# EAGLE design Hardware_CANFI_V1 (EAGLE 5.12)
DIELECTRIC: X5R; OC_FARNELL: unknown; OC_RADIOSPARES: 8006936; SUPPLIER: COILCRAFT; VOLTAGE: 16V

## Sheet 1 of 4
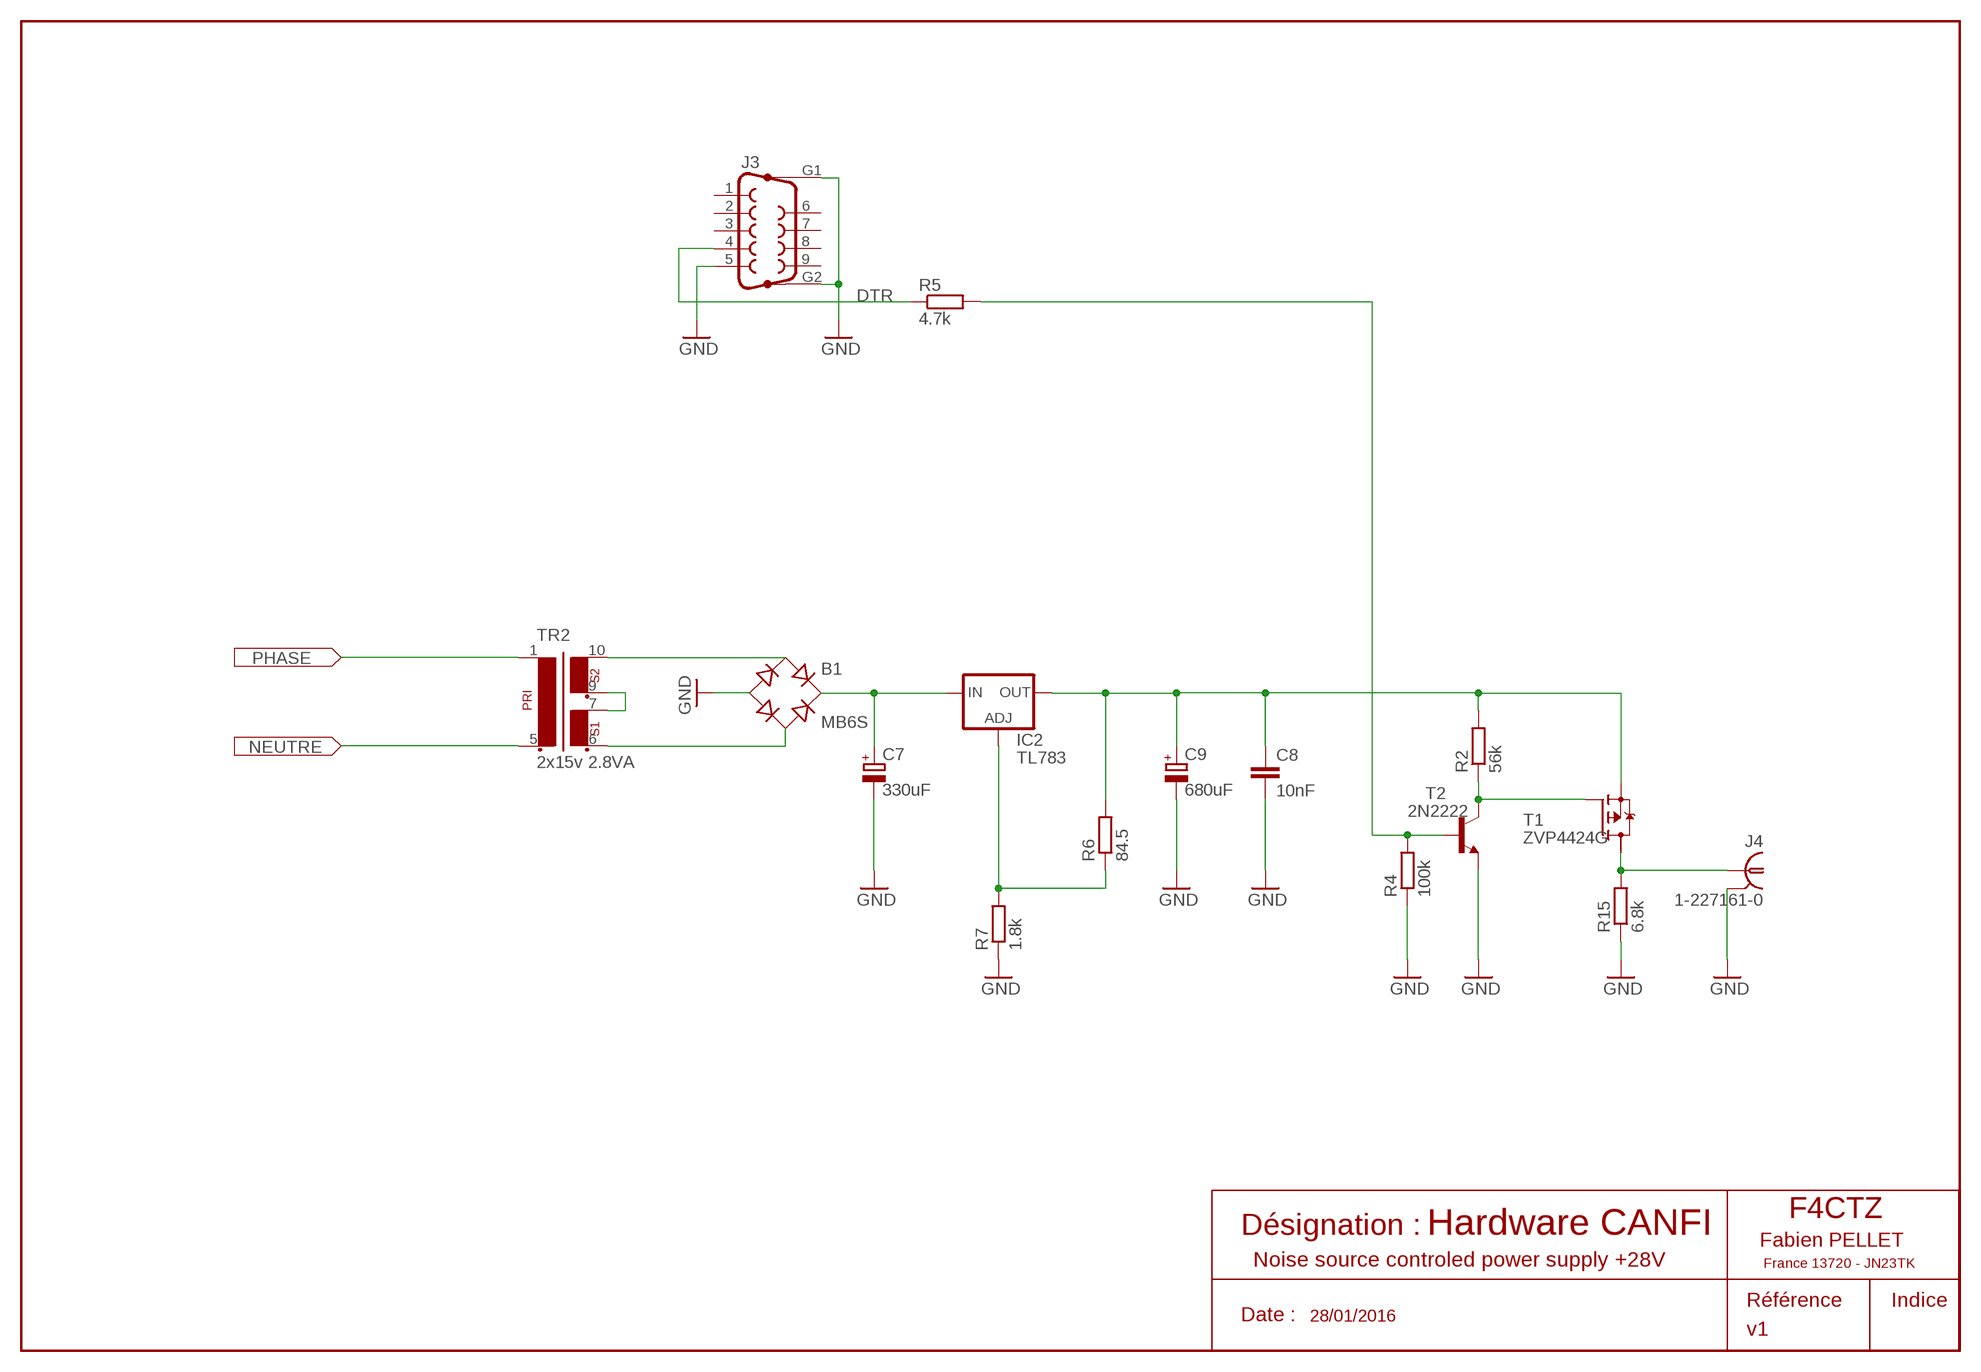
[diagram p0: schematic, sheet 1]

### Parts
B1  MB6S  MB8S  [SOIC-4]
C7  330uF  CPOL-EUE5-13  [E5-13]
C8  10nF  C-EUC0603  [C0603]
C9  680uF  CPOL-EUE5-10.5  [E5-10,5]
IC2  TL783  LM317TS  [317TS]
J3  F09HP  [F09HP]
J4  1-227161-0  [AMP_227161]
R2  56k  R-EU_R0603  [R0603]
R4  100k  R-EU_R0603  [R0603]
R5  4.7k  R-EU_R0603  [R0603]
R6  84.5  R-EU_R0603  [R0603]
R7  1.8k  R-EU_R0603  [R0603]
R15  6.8k  R-EU_R0603  [R0603]
T1  ZVP4424G  BSP170P  [SOT223]
T2  2N2222  2N2222-NPN-TO92-EBC  [TO92-EBC]
TR2  2x15v 2.8VA  EI30-2  [EI30-2]

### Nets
DTR: J3.4 R5.1
GND: B1.- C7.- C8.2 C9.- J3.5 J3.G1 J3.G2 J4.2(GND) R4.1 R7.1 R15.1 T2.E ; also sheet 2,3
N$8: R4.2 R5.2 T2.B
N$10: R2.1 T1.1(G) T2.C
N$12 [ALIM]: B1.~1(AC1) TR2.10
N$13 [ALIM]: TR2.7 TR2.9
N$14 [ALIM]: B1.~2(AC2) TR2.6
N$15 [ALIM]: C8.1 C9.+ IC2.2(OUT) R2.2 R6.2 T1.3(S)
N$18: IC2.1(ADJ) R6.1 R7.2
N$19 [ALIM]: B1.+ C7.+ IC2.3(IN)
N$21: J4.1 R15.2 T1.4(D1)
NEUTRE [HIGH_VOLTAGE]: TR2.5 ; also sheet 3
PHASE [HIGH_VOLTAGE]: TR2.1 ; also sheet 3
Unconnected: J3.1 J3.2 J3.3 J3.6 J3.7 J3.8 J3.9 T1.2(D)

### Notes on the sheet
- Hardware CANFI
- Noise source controled power supply +28V
- 28/01/2016

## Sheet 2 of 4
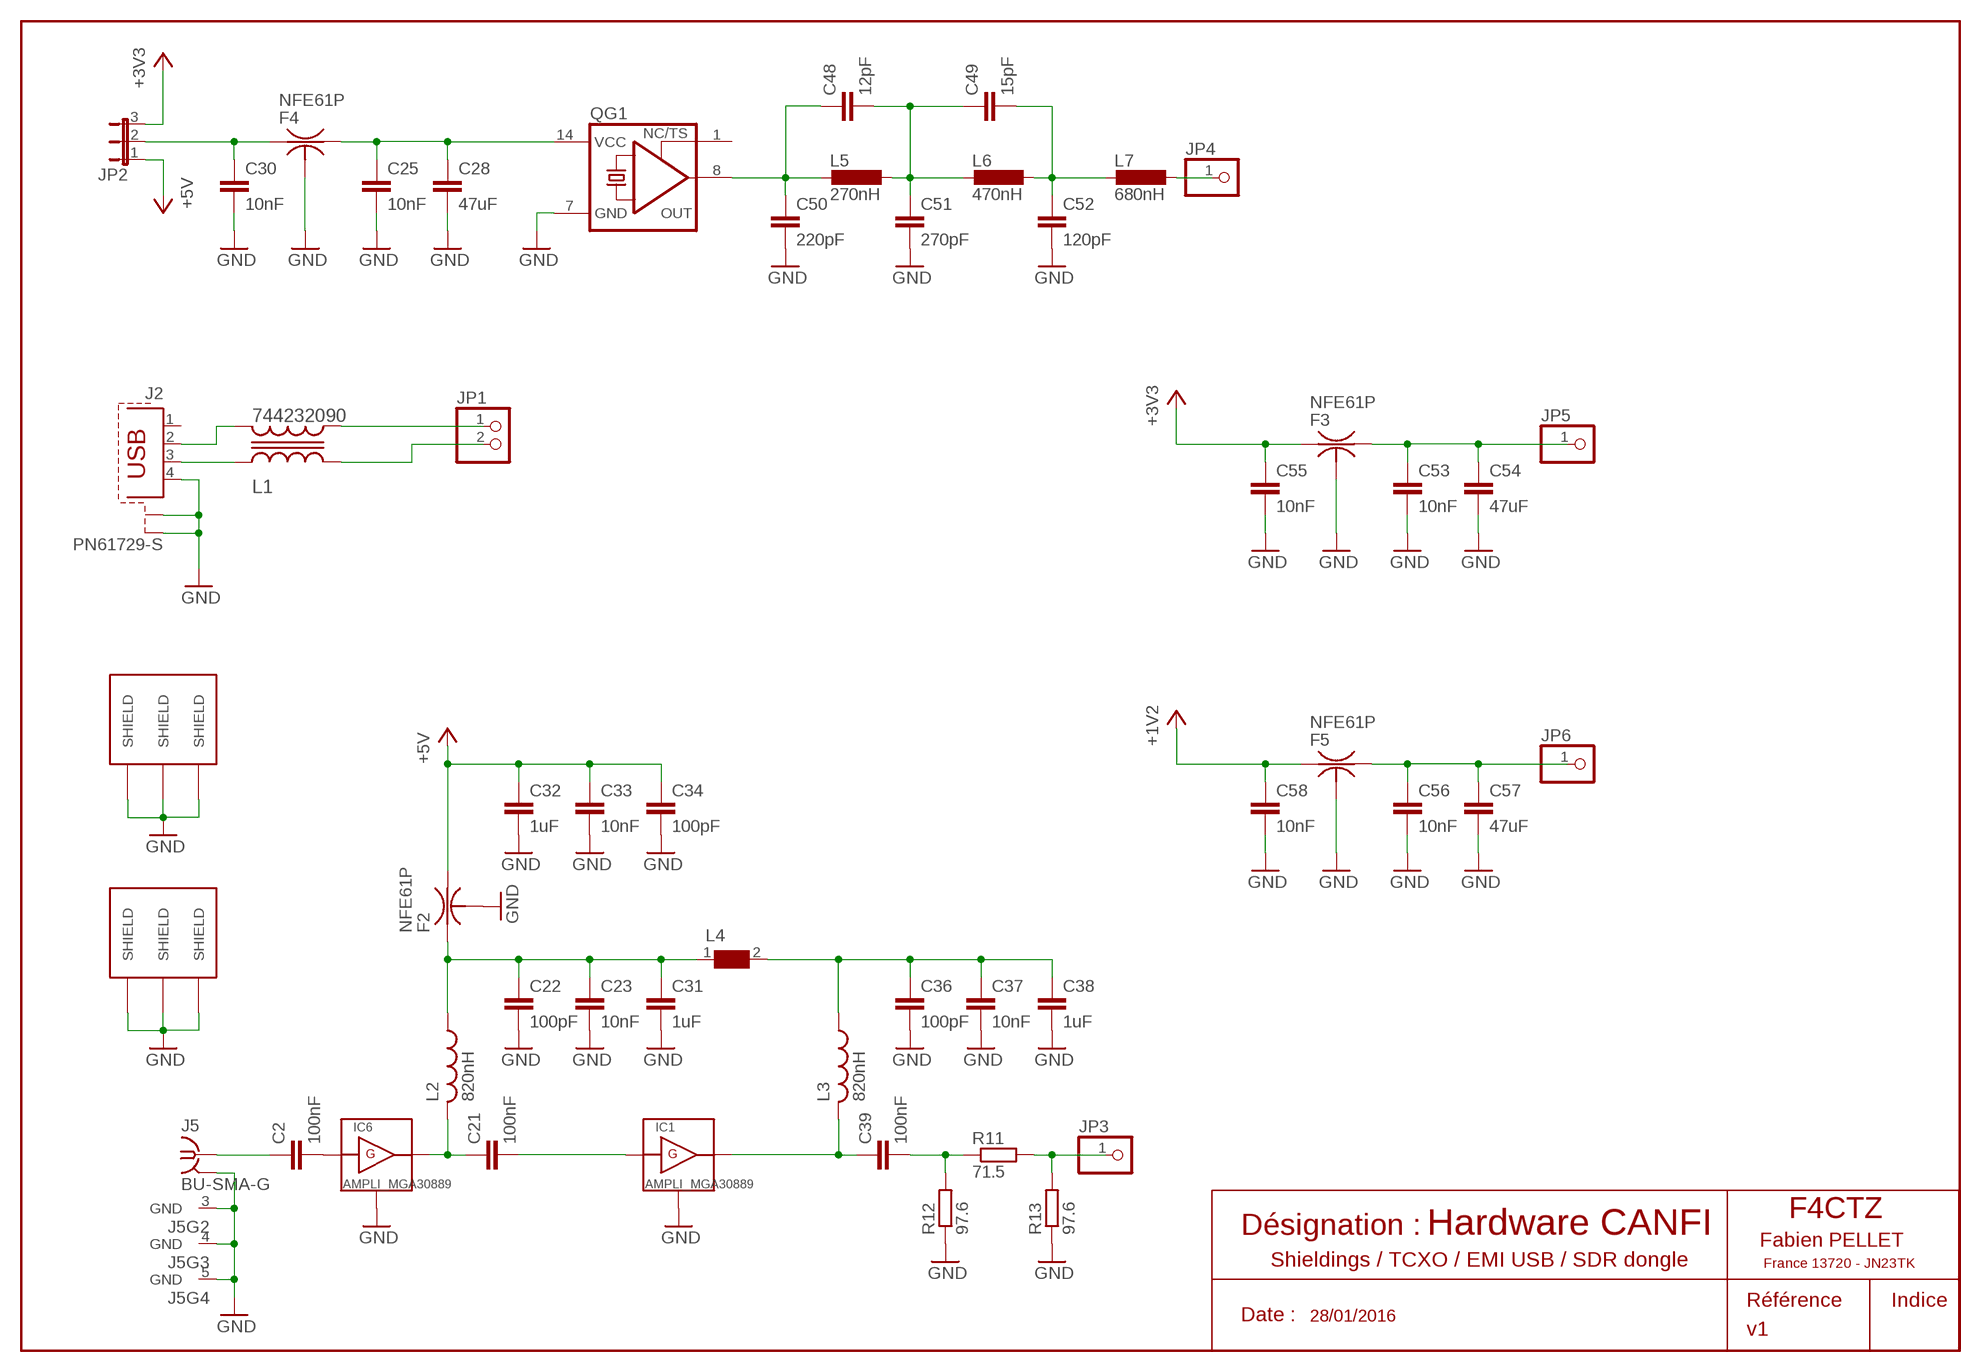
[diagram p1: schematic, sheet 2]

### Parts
C2  100nF  C-EUC0603  [C0603]
C21  100nF  C-EUC0603  [C0603]
C22  100pF  C-EUC0603  [C0603]
C23  10nF  C-EUC0603  [C0603]
C25  10nF  C-EUC0603  [C0603]
C28  47uF  C-EUC1210  [C1210]
C30  10nF  C-EUC0603  [C0603]
C31  1uF  C-EUC0603  [C0603]
C32  1uF  C-EUC0603  [C0603]
C33  10nF  C-EUC0603  [C0603]
C34  100pF  C-EUC0603  [C0603]
C36  100pF  C-EUC0603  [C0603]
C37  10nF  C-EUC0603  [C0603]
C38  1uF  C-EUC0603  [C0603]
C39  100nF  C-EUC0603  [C0603]
C48  12pF  C-EUC0603  [C0603]
C49  15pF  C-EUC0603  [C0603]
C50  220pF  C-EUC0603  [C0603]
C51  270pF  C-EUC0603  [C0603]
C52  120pF  C-EUC0603  [C0603]
C53  10nF  C-EUC0603  [C0603]
C54  47uF  C-EUC1210  [C1210]
C55  10nF  C-EUC0603  [C0603]
C56  10nF  C-EUC0603  [C0603]
C57  47uF  C-EUC1210  [C1210]
C58  10nF  C-EUC0603  [C0603]
F2  NFE61P  [NFE61P]
F3  NFE61P  [NFE61P]
F4  NFE61P  [NFE61P]
F5  NFE61P  [NFE61P]
IC1  AMPLI_MGA30889  [SOT89]
IC6  AMPLI_MGA30889  [SOT89]
J2  PN61729-S  [PN61729-S]
J5  BU-SMA-G  [BU-SMA-G]
JP1  PINHD-1X2  [1X02]
JP2  JP2E  [JP2]
JP3  PINHD-1X1  [1X01]
JP4  PINHD-1X1  [1X01]
JP5  PINHD-1X1  [1X01]
JP6  PINHD-1X1  [1X01]
L1  744232090  1206USB  [1206USB]
L2  820nH  L-USL2012C  [L2012C]
L3  820nH  L-USL2012C  [L2012C]
L4  WE-CBF_0603  [0603]
L5  270nH  L-EUL2825P  [L2825P]
L6  470nH  L-EUL2825P  [L2825P]
L7  680nH  L-EUL2825P  [L2825P]
QG1  XO-14  [DIL14S]
R11  71.5  R-EU_R0603  [R0603]
R12  97.6  R-EU_R0603  [R0603]
R13  97.6  R-EU_R0603  [R0603]
SH1  CAPOT_403.16  [CAPOT_403.16]
SH2  CAPOTMS355-10  [CAPOT_MS355-10]

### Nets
+1V2: C58.1 F5.1 ; also sheet 3
+3V3 [ALIM]: C55.1 F3.1 JP2.3 ; also sheet 3
+5V [ALIM]: C32.1 C33.1 C34.1 F2.3 JP2.1 ; also sheet 3
D+: J2.3 L1.P$1
D+*: JP1.2 L1.P$2
D-: J2.2 L1.P$4
D-*: JP1.1 L1.P$3
GND: C22.2 C23.2 C25.2 C28.2 C30.2 C31.2 C32.2 C33.2 C34.2 C36.2 C37.2 C38.2 C50.2 C51.2 C52.2 C53.2 C54.2 C55.2 C56.2 C57.2 C58.2 F2.2 F3.2 F4.2 F5.2 IC1.2(GND) IC6.2(GND) J2.4 J2.S1 J2.S2 J5.2(GND) J5.3(GND) J5.4(GND) J5.5(GND) QG1.7(GND) R12.1 R13.1 SH1.1(SHIELD) SH1.2(SHIELD) SH1.3(SHIELD) SH2.P$1(SHIELD) SH2.P$2(SHIELD) SH2.P$3(SHIELD) ; also sheet 1,3
N$3 [RF]: C48.1 C50.1 L5.2 QG1.8(OUT)
N$4 [RF]: C48.2 C49.1 C51.1 L5.1 L6.2
N$6: C2.1 J5.1
N$9 [RF]: C49.2 C52.1 L6.1 L7.2
N$11 [RF]: C2.2 IC6.1(IN)
N$26: C30.1 F4.1 JP2.2
N$28 [RF]: C21.1 IC6.3(OUT) L2.2
N$29: C22.1 C23.1 C31.1 F2.1 L2.1 L4.1
N$30: C25.1 C28.1 F4.3 QG1.14(VCC)
N$31 [RF]: C39.1 IC1.3(OUT) L3.2
N$32: C36.1 C37.1 C38.1 L3.1 L4.2
N$33 [RF]: C21.2 IC1.1(IN)
N$34 [RF]: JP3.1 R11.2 R13.2
N$35 [RF]: JP4.1 L7.1
N$36 [RF]: C39.2 R11.1 R12.2
N$37: C53.1 C54.1 F3.3 JP5.1
N$39: C56.1 C57.1 F5.3 JP6.1
Unconnected: J2.1 QG1.1(TS)

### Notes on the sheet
- Hardware CANFI
- Shieldings / TCXO / EMI USB / SDR dongle
- 28/01/2016

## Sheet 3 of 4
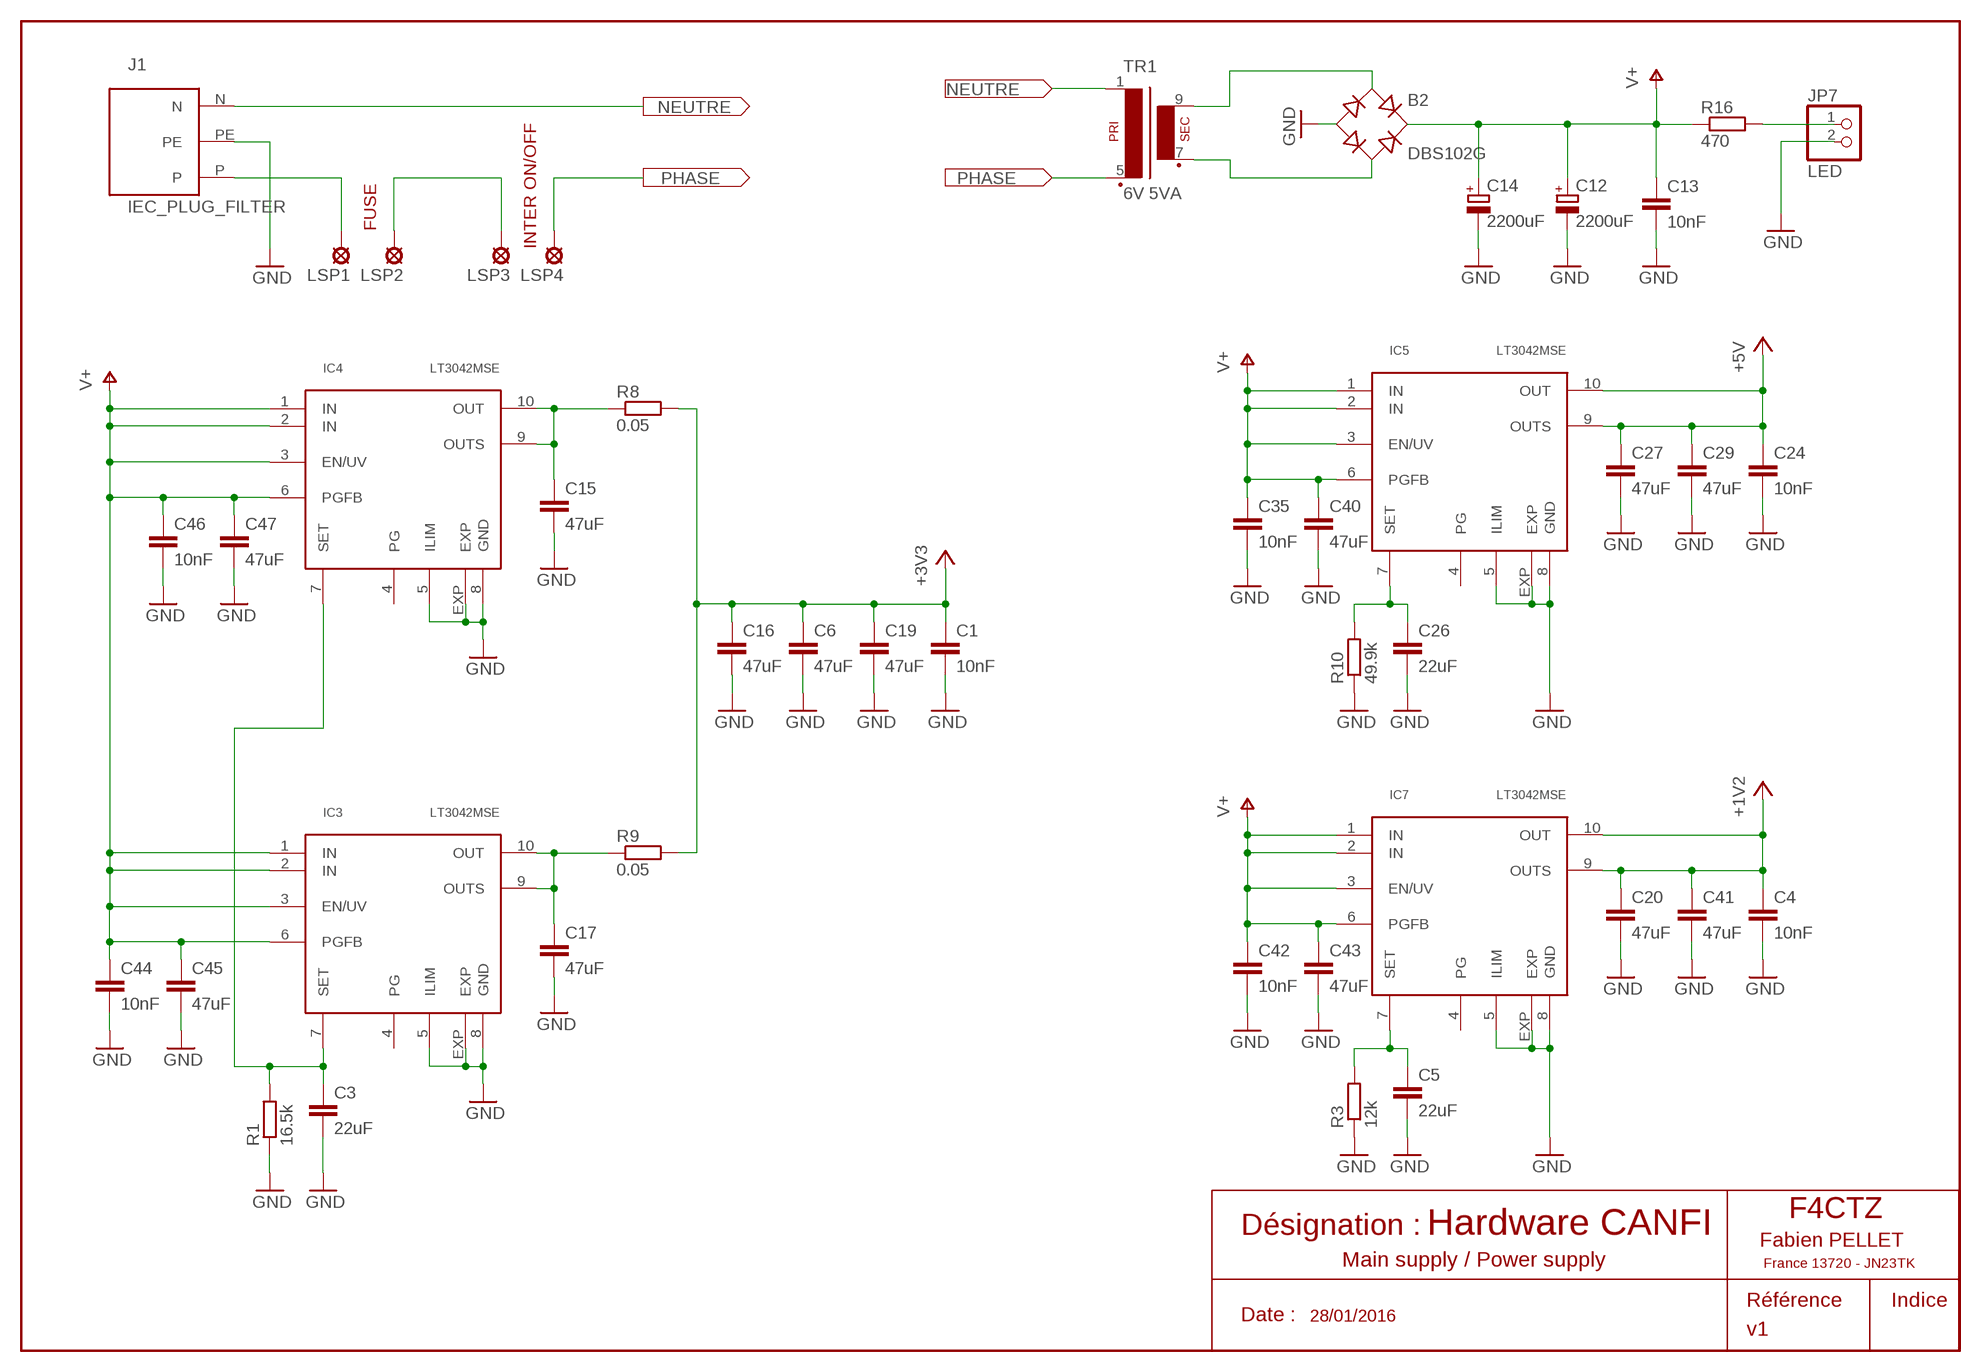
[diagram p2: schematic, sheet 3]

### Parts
B2  DBS102G  [DBS]
C1  10nF  C-EUC0603  [C0603]
C3  22uF  C-EUC0805  [C0805]
C4  10nF  C-EUC0603  [C0603]
C5  22uF  C-EUC0805  [C0805]
C6  47uF  C-EUC1210  [C1210]
C12  2200uF  CPOL-EUE5-10.5  [E5-10,5]
C13  10nF  C-EUC0603  [C0603]
C14  2200uF  CPOL-EUE5-10.5  [E5-10,5]
C15  47uF  C-EUC1210  [C1210]
C16  47uF  C-EUC1210  [C1210]
C17  47uF  C-EUC1210  [C1210]
C19  47uF  C-EUC1210  [C1210]
C20  47uF  C-EUC1210  [C1210]
C24  10nF  C-EUC0603  [C0603]
C26  22uF  C-EUC0805  [C0805]
C27  47uF  C-EUC1210  [C1210]
C29  47uF  C-EUC1210  [C1210]
C35  10nF  C-EUC0603  [C0603]
C40  47uF  C-EUC1210  [C1210]
C41  47uF  C-EUC1210  [C1210]
C42  10nF  C-EUC0603  [C0603]
C43  47uF  C-EUC1210  [C1210]
C44  10nF  C-EUC0603  [C0603]
C45  47uF  C-EUC1210  [C1210]
C46  10nF  C-EUC0603  [C0603]
C47  47uF  C-EUC1210  [C1210]
IC3  LT3042MSE  [MSOP10@2]
IC4  LT3042MSE  [MSOP10@2]
IC5  LT3042MSE  [MSOP10@2]
IC7  LT3042MSE  [MSOP10@2]
J1  IEC_PLUG_FILTER  [FN9226-YY-02]
JP7  LED  PINHD-1X2  [1X02]
LSP1  MCS08  [MCS08]
LSP2  MCS08  [MCS08]
LSP3  MCS08  [MCS08]
LSP4  MCS08  [MCS08]
R1  16.5k  R-EU_R0603  [R0603]
R3  12k  R-EU_R0603  [R0603]
R8  0.05  R-EU_R2512  [R2512]
R9  0.05  R-EU_R2512  [R2512]
R10  49.9k  R-EU_R0603  [R0603]
R16  470  R-EU_R0603  [R0603]
TR1  6V 5VA  EI42-1  [EI42-1]

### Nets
+1V2: C4.1 C20.1 C41.1 IC7.9(OUTS) IC7.10(OUT) ; also sheet 2
+3V3 [ALIM]: C1.1 C6.1 C16.1 C19.1 R8.2 R9.2 ; also sheet 2
+5V [ALIM]: C24.1 C27.1 C29.1 IC5.9(OUTS) IC5.10(OUT) ; also sheet 2
GND: B2.- C1.2 C3.2 C4.2 C5.2 C6.2 C12.- C13.2 C14.- C15.2 C16.2 C17.2 C19.2 C20.2 C24.2 C26.2 C27.2 C29.2 C35.2 C40.2 C41.2 C42.2 C43.2 C44.2 C45.2 C46.2 C47.2 IC3.5(ILIM) IC3.8(GND) IC3.EXP IC4.5(ILIM) IC4.8(GND) IC4.EXP IC5.5(ILIM) IC5.8(GND) IC5.EXP IC7.5(ILIM) IC7.8(GND) IC7.EXP J1.PE JP7.2 R1.1 R3.1 R10.1 ; also sheet 1,2
N$1 [HIGH_VOLTAGE]: J1.P LSP1.MP
N$2: C5.1 IC7.7(SET) R3.2
N$5: C3.1 IC3.7(SET) IC4.7(SET) R1.2
N$7 [ALIM]: C15.1 IC4.9(OUTS) IC4.10(OUT) R8.1
N$16 [ALIM]: B2.AC1 TR1.9(S4)
N$17 [ALIM]: B2.AC2 TR1.7(S3)
N$22 [ALIM]: C17.1 IC3.9(OUTS) IC3.10(OUT) R9.1
N$23 [HIGH_VOLTAGE]: LSP2.MP LSP3.MP
N$24 [ALIM]: JP7.1 R16.2
N$27: C26.1 IC5.7(SET) R10.2
NEUTRE [HIGH_VOLTAGE]: J1.N TR1.1 ; also sheet 1
PHASE [HIGH_VOLTAGE]: LSP4.MP TR1.5(P2) ; also sheet 1
V+ [ALIM]: B2.+ C12.+ C13.1 C14.+ C35.1 C40.1 C42.1 C43.1 C44.1 C45.1 C46.1 C47.1 IC3.1(IN) IC3.2(IN) IC3.3(EN/UV) IC3.6(PGFB) IC4.1(IN) IC4.2(IN) IC4.3(EN/UV) IC4.6(PGFB) IC5.1(IN) IC5.2(IN) IC5.3(EN/UV) IC5.6(PGFB) IC7.1(IN) IC7.2(IN) IC7.3(EN/UV) IC7.6(PGFB) R16.1
Unconnected: IC3.4(PG) IC4.4(PG) IC5.4(PG) IC7.4(PG)

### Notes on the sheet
- FUSE
- INTER ON/OFF
- Hardware CANFI
- Main supply / Power supply
- 28/01/2016

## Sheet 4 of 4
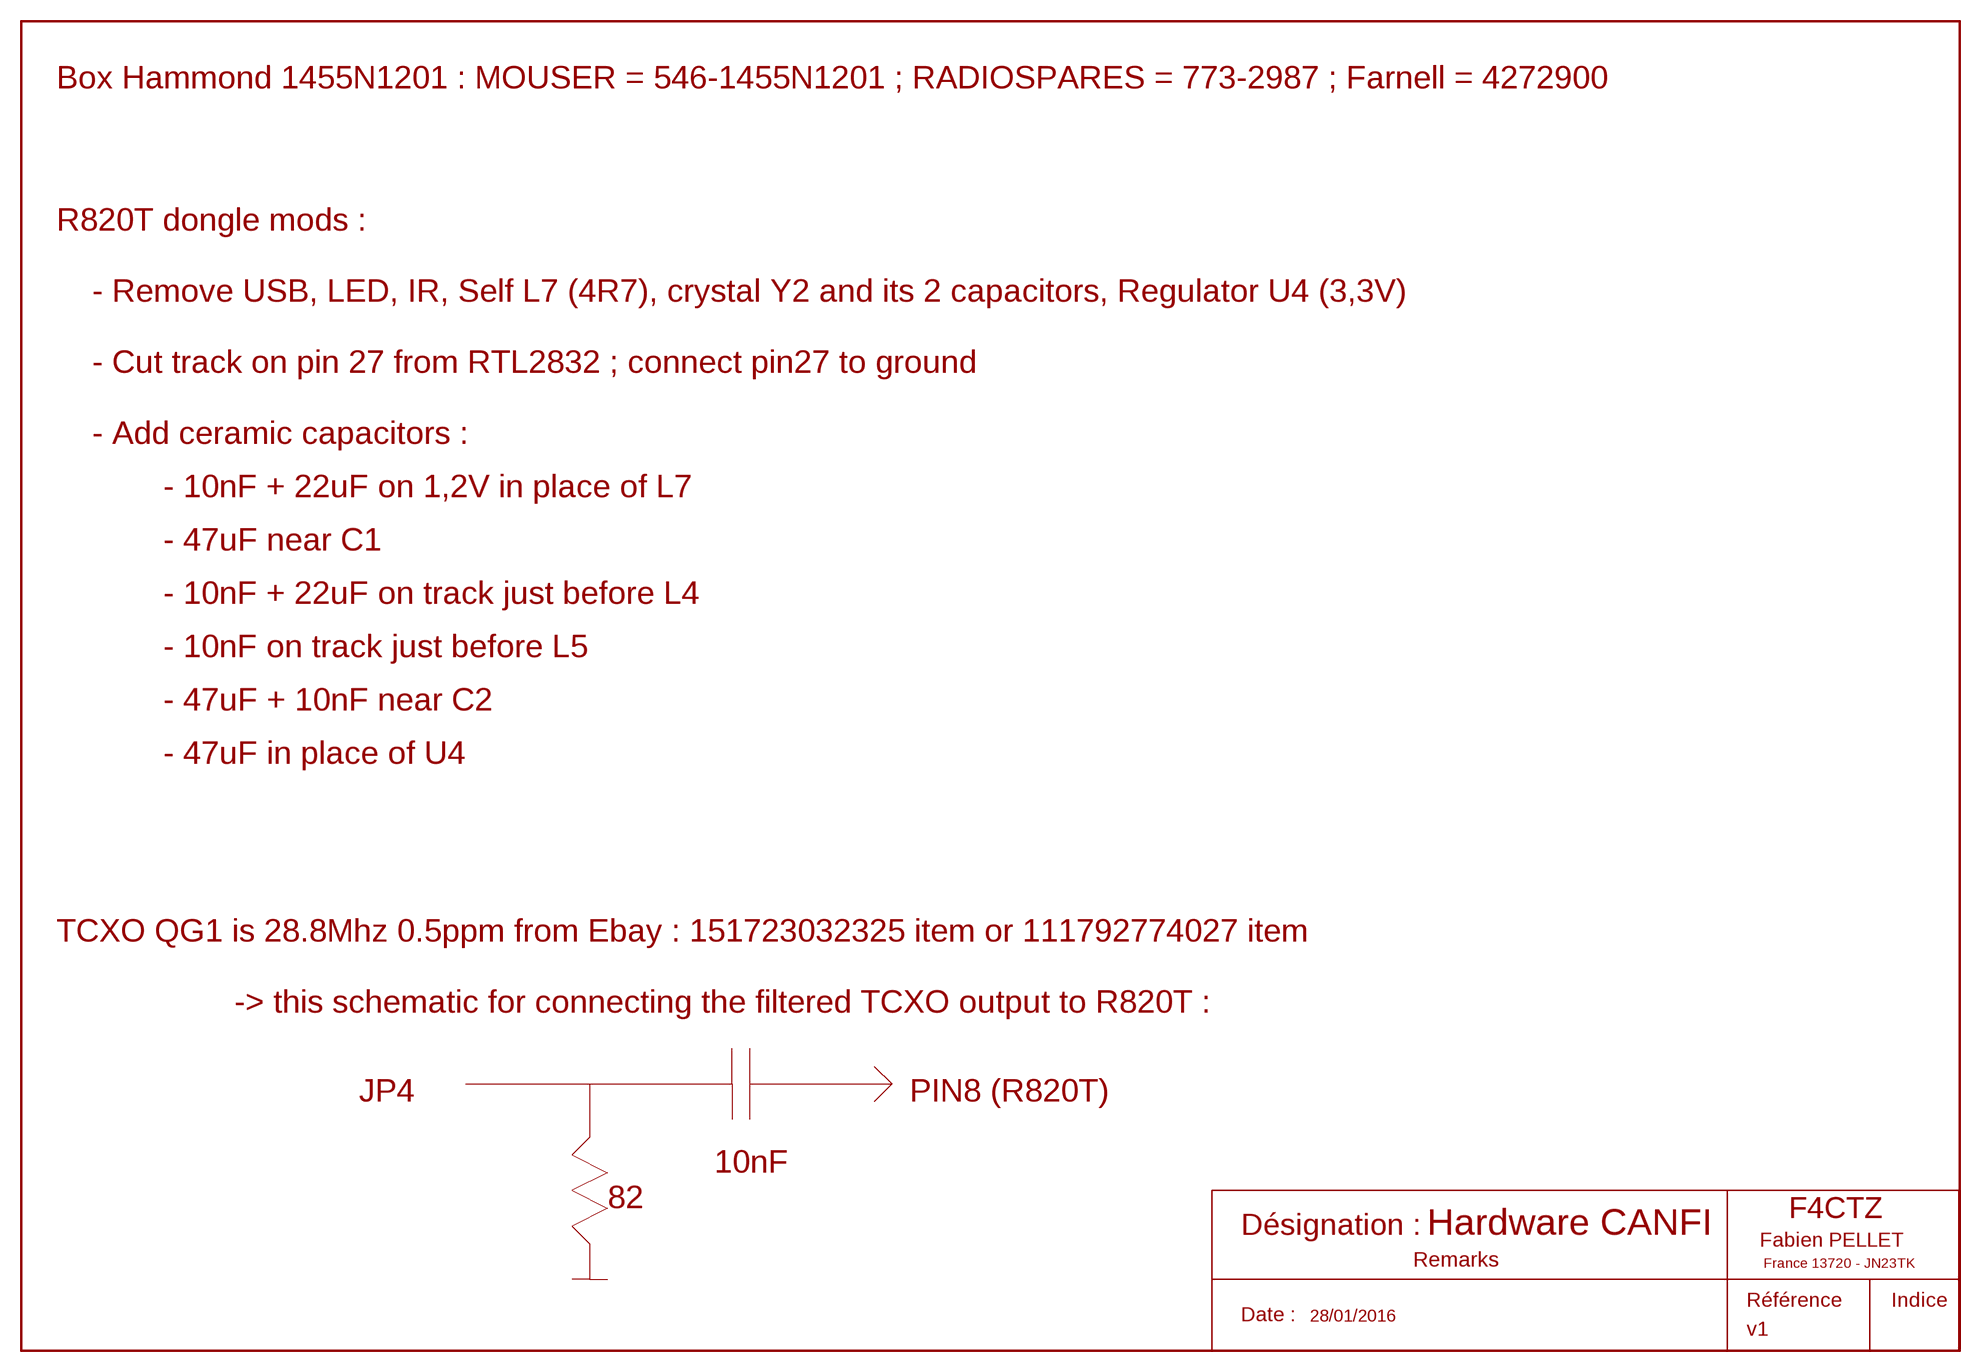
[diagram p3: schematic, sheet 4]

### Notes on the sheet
- Box Hammond 1455N1201 : MOUSER = 546-1455N1201 ; RADIOSPARES = 773-2987 ; Farnell = 4272900
- R820T dongle mods :
- - Remove USB, LED, IR, Self L7 (4R7), crystal Y2 and its 2 capacitors, Regulator U4 (3,3V)
- - Cut track on pin 27 from RTL2832 ; connect pin27 to ground
- - Add ceramic capacitors :
- - 10nF + 22uF on 1,2V in place of L7
- - 47uF near C1
- - 10nF + 22uF on track just before L4
- - 10nF on track just before L5
- - 47uF + 10nF near C2
- - 47uF in place of U4
- TCXO QG1 is 28.8Mhz 0.5ppm from Ebay : 151723032325 item or 111792774027 item
- -> this schematic for connecting the filtered TCXO output to R820T :
- JP4 | PIN8 (R820T)
- 10nF
- 82
- Hardware CANFI
- Remarks
- 28/01/2016

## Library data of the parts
B1 = rectifier:MB*S: Bridge Rectifier Source: http://www.fairchildsemi.com/ds/MB/MB6S.pdf
B2 = rectifier:DB?*G: Single Phase 1.0 AMP Glass Passivated Bridge Rectifier Taiwan Semiconductor Co.,Ltd. - TSC Source: http://www.taiwansemi.com/TSCbig5/ezcatfiles/cust/img/img/db101g.pdf http://www.ts.com.tw/db/pictures/modules/PDT/PDT060207001/DBLS201G.pdf
C1-C6 C8 C13 C15-C17 C19-C58 = rcl:C-EU: CAPACITOR, European symbol
C7 C9 C12 C14 = rcl:CPOL-EU: POLARIZED CAPACITOR, European symbol
F2-F5 = murata-filter:NFE61P
IC1 IC6 = fabien-rf:AMPLI_*; MPN: MGA30889; OC_FARNELL: 1865178; SUPPLIER: AVAGO
IC2 = v-reg:LM317TS: VOLTAGE REGULATOR
IC3-IC5 IC7 = linear-technology:LT3042; MF: LINEAR TECHNOLOGY; MPN: LT3042EMSE#PBF; OC_FARNELL: 2475652
J1 = fabien:IEC_PLUG_FILTER
J2 = con-berg:PN61729-S: BERG USB connector; OC_FARNELL: unknown; OC_NEWARK: unknown
J3 = con-subd:F09HP: SUB-D; OC_FARNELL: unknown; OC_NEWARK: unknown
J4 = con-coax:?227161*: JACK, RIGHT ANGLE, 50 OHM, PCB, BNC; MF: TYCO ELECTRONICS; MPN: 1-227161; OC_FARNELL: unknown; OC_NEWARK: 33B3200
J5 = con-coax:BU-SMA-G: FEMALE SMA CONNECTOR Radiall distributor RS 193-9117; OC_FARNELL: unknown; OC_NEWARK: unknown
JP1 JP7 = pinhead:PINHD-1X2: PIN HEADER
JP2 = jumper:JP2E: JUMPER
JP3-JP6 = pinhead:PINHD-1X1: PIN HEADER
L1 = inductor-coilcraft:1206USB
L2 L3 = rcl:L-US: INDUCTOR, American symbol
L4 = Wuerth_Elektronik_eiSos_V4:WE-CBF: SMD EMI Suppression Ferrite Beads WE-CBF
L5-L7 = rcl:L-EU: INDUCTOR, European symbol
LSP1-LSP4 = solpad:MCS08: SOLDER PAD
QG1 = crystal:XO-: CRYSTAL; OC_FARNELL: unknown; OC_NEWARK: unknown
R1-R13 R15 R16 = rcl:R-EU_: RESISTOR, European symbol
SH1 = fabien-rf:CAPOT*; MPN: 403.16; OC_RADIOSPARES: 237-2751; SUPPLIER: OKW
SH2 = fabien-rf:CAPOT*
T1 = transistor-fet:BSP170P: SIPMOS(R) Small-Signal-Transistor P-Channel, Enhancement mode Source: http://www.infineon.com/upload/Document/BSP170P_Rev2.4.pdf
T2 = transistor-neu-to92:*-NPN-: NPN Transistror
TR1 = trafo:EI42-1: TRANSFORMER 1 primary winding, 1 secondary winding ERA
TR2 = trafo:EI30-2: TRANSFORMER 1 primary winding, 2 secondary windings ERA

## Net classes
1 HIGH_VOLTAGE: clearance 1 mm
2 ALIM: clearance 0.3 mm
3 RF: clearance 0.3 mm

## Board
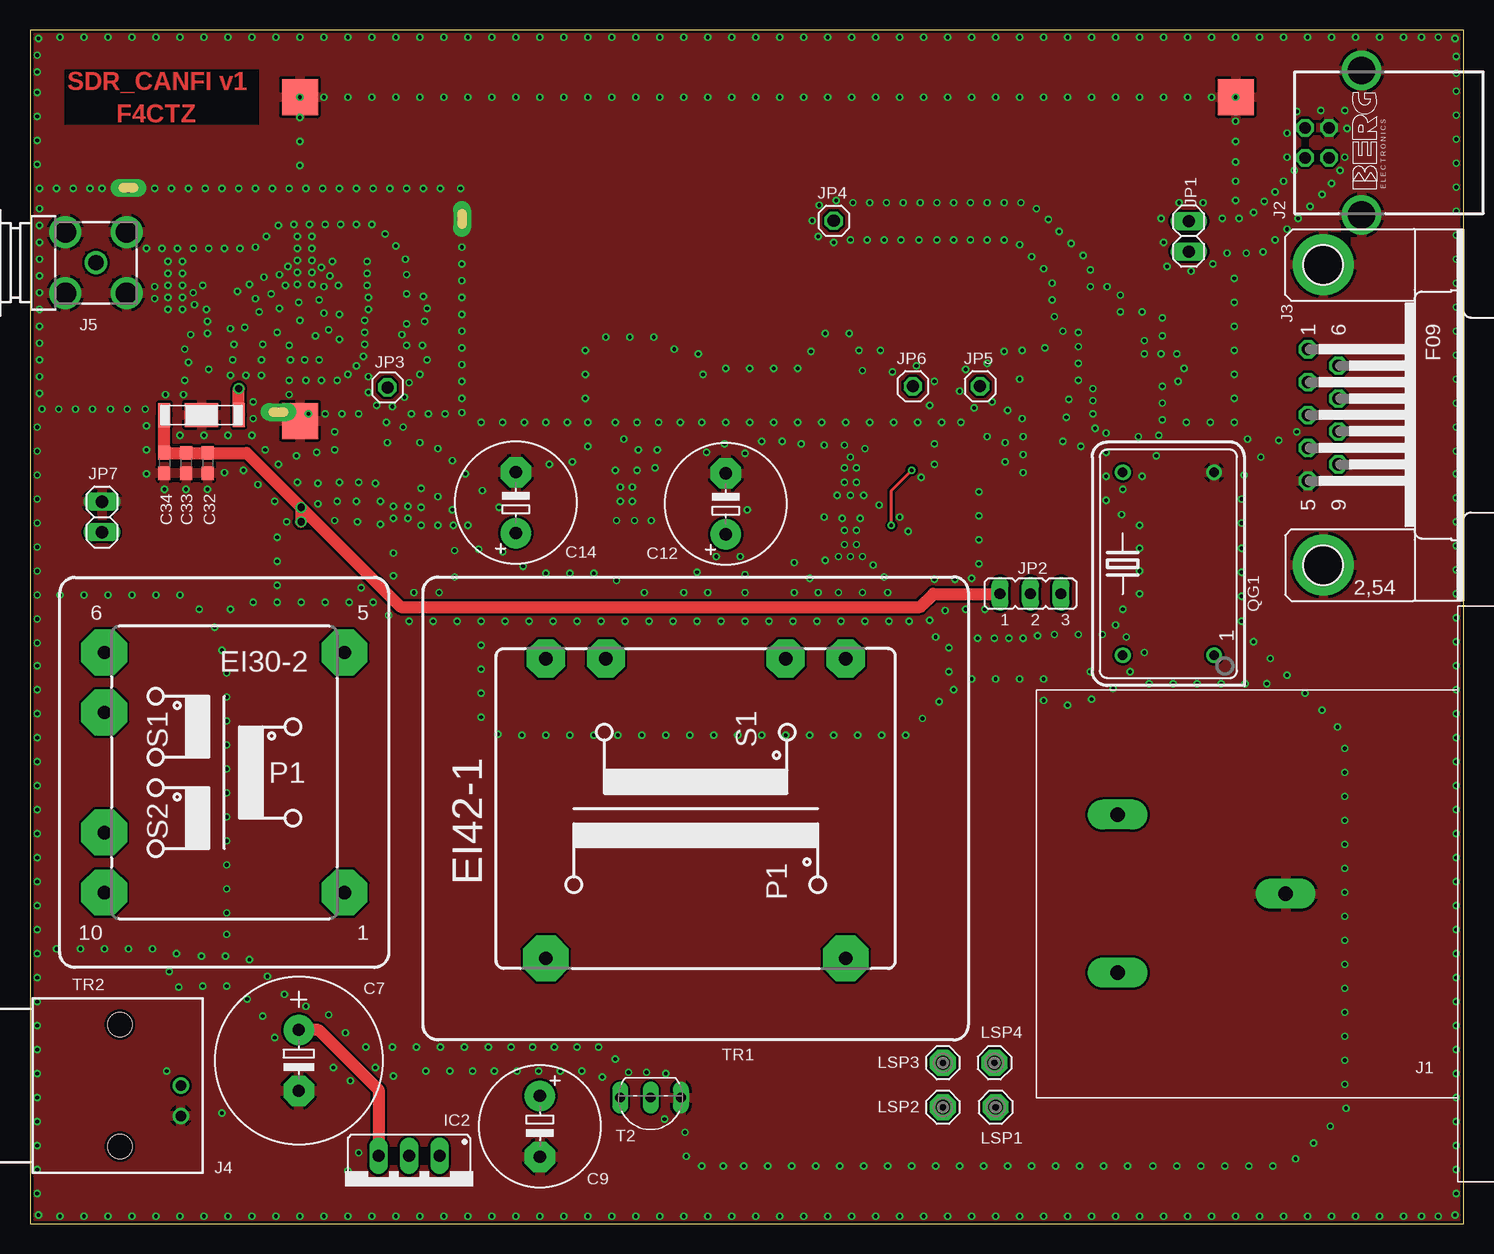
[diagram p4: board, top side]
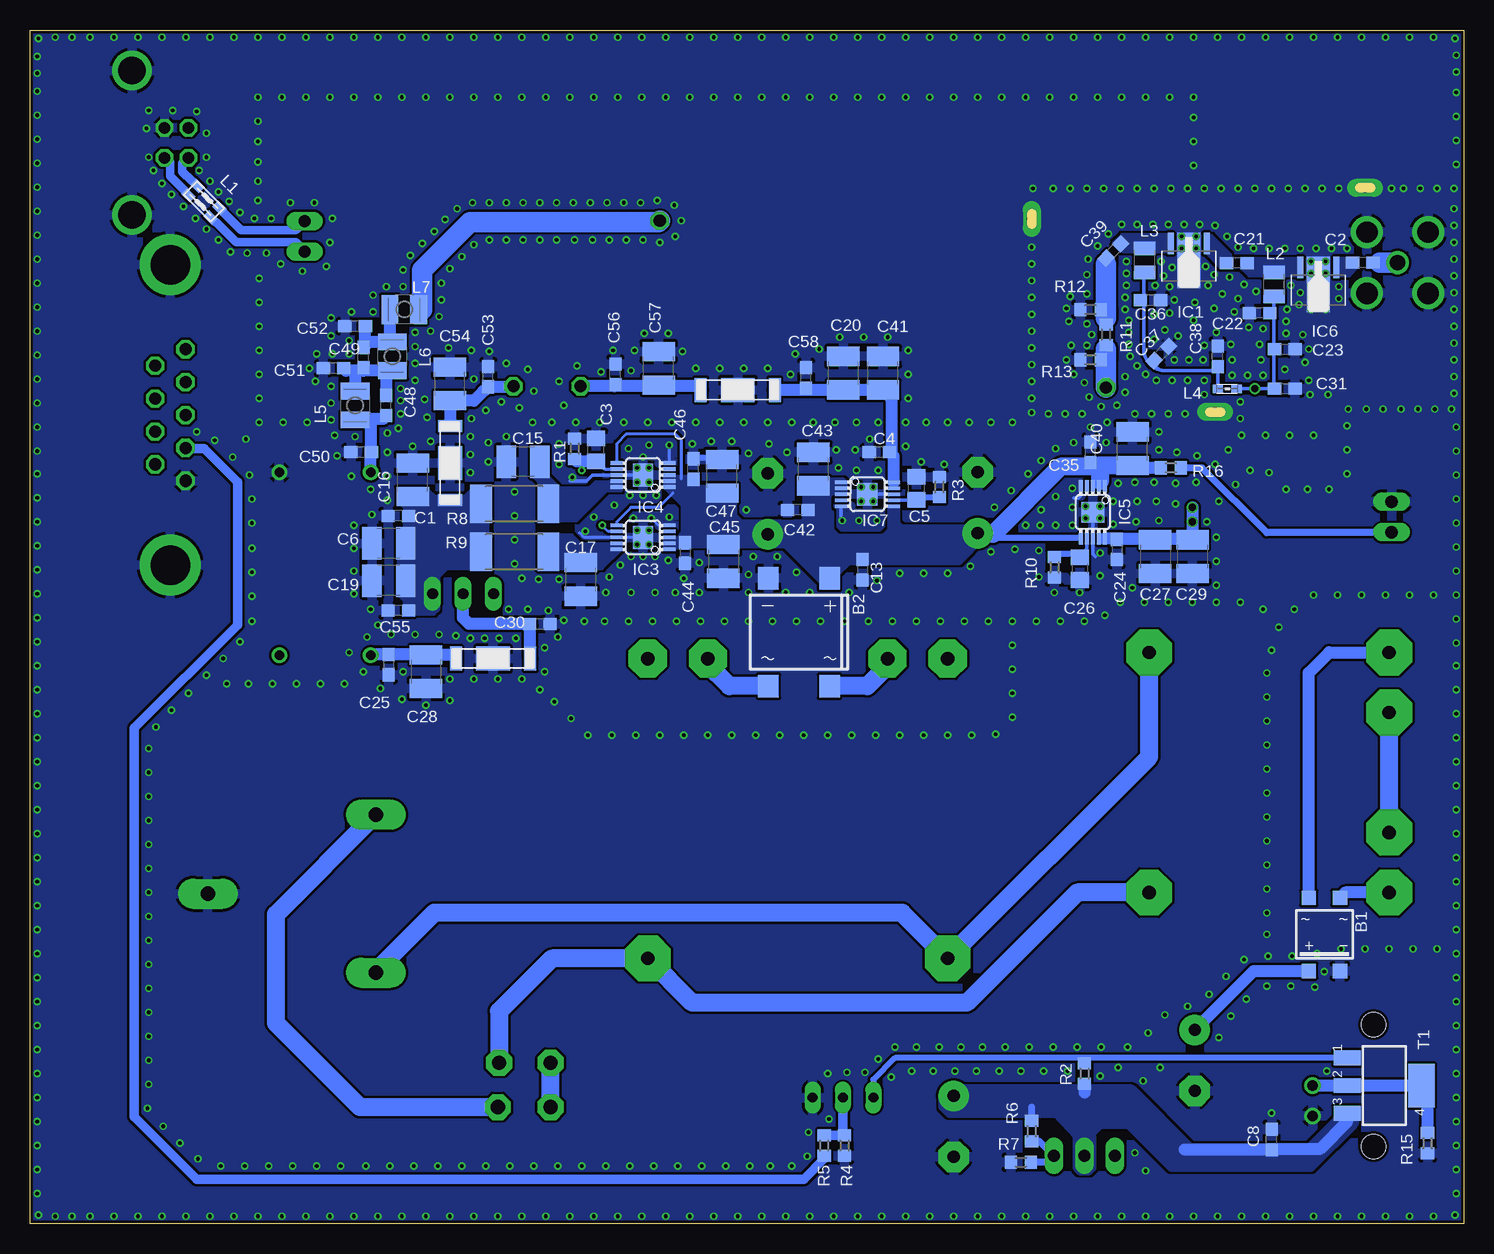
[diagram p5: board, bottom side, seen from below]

Size 119.5 x 99.5 mm. Coordinates in mm from the lower left corner, seen from the top.
Outline: 0,0 119.5,0 119.5,99.5 0,99.5 0,0
Copper layers (1*16): Top 0.035mm / dielectric 1.5mm / Bottom 0.035mm
Design rules "dirt_cheap_dirty_boards.v1 *": minimum track width 5mil, minimum drill 12mil, track to track 0.2mm, track to pad 0.2mm, pad to pad 0.2mm, via to via 0.2mm, smd to smd 0mil, copper to edge 10mil, drill to drill 10mil, minimum pad ring 10mil, minimum via ring 6mil, stop-mask expansion 2mil, vias tented up to drill 25mil, thermal gap 10mil
tRestrict: area 2.9,91.6 to 19.1,96.2

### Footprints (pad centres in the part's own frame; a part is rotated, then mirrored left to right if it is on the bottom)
SOIC-4 = smd 1.2 x 1.2: + 1.3,3.05; - -1.3,3.05; ~1 -1.3,-3.05; ~2 1.3,-3.05
DBS = smd 1.7 x 1.9: + -2.55,-4.5; - 2.55,-4.5; AC1 -2.55,4.5; AC2 2.55,4.5
C0603 = smd 1.1 x 1: 1 -0.85,0; 2 0.85,0
C0805 = smd 1.3 x 1.5: 1 -0.95,0; 2 0.95,0
C1210 = smd 1.6 x 2.7: 1 -1.4,0; 2 1.4,0
E5-13 = drill 1.016 pad 2.54 round: + -2.54,0 | drill 1.016 pad 2.54 octagon: - 2.54,0
E5-10,5 = drill 1.016 pad 2.54 round: + -2.54,0 | drill 1.016 pad 2.54 octagon: - 2.54,0
NFE61P = smd 1 x 2: 1 -3.1,0; 3 3.1,0 | smd 2.8 x 2: 2 0,0
SOT89 = smd 0.5 x 1.8: 1 -1.5,-1.9; 3 1.5,-1.9 | smd 1.9 x 4.6: 2 0,-0.5
317TS = drill 1.016 long: 1 -2.54,-2.54; 2 0,-2.54; 3 2.54,-2.54
MSOP10@2 = smd 0.3 x 1: 1 -1,-2.2; 2 -0.5,-2.2; 3 0,-2.2; 4 0.5,-2.2; 5 1,-2.2; 6 1,2.2; 7 0.5,2.2; 8 0,2.2; 9 -0.5,2.2; 10 -1,2.2 | smd 1.9 x 1.7: EXP 0,0
FN9226-YY-02 = drill 1.2 pad 2.5 long: N 13.625,6.6; P 13.625,-6.6; PE -0.375,0
PN61729-S = drill 0.95 octagon: 1 1.25,4.71; 2 -1.25,4.71; 3 -1.25,2.71; 4 1.25,2.71 | drill 2.3 pad 2.9 round: S1 -6.02,0; S2 6.02,0
F09HP = drill 1.016 octagon: 1 -5.486,-1.27; 2 -2.743,-1.27; 3 0,-1.27; 4 2.743,-1.27; 5 5.486,-1.27; 6 -4.115,1.27; 7 -1.372,1.27; 8 1.372,1.27; 9 4.115,1.27 | drill 3.302 pad 5.08 round: G1 -12.522,0; G2 12.522,0
AMP_227161 = drill 0.9 pad 1.27 round: 1 0,-5.08; 2 -2.54,-5.08 | hole 2: -5.08,0; 5.08,0
BU-SMA-G = drill 1.27 round: 1 0,0 | drill 1.778 round: 2 -2.55,2.55; 3 2.55,2.55; 4 2.55,-2.55; 5 -2.55,-2.55
1X02 = drill 1.016 long: 1 -1.27,0; 2 1.27,0
JP2 = drill 0.914 long: 1 -2.54,0; 2 0,0; 3 2.54,0
1X01 = drill 1.016 octagon: 1 0,0
1206USB = smd 1 x 0.7: P$1 1.3,0.55; P$2 -1.3,0.55; P$3 -1.3,-0.55; P$4 1.3,-0.55
L2012C = smd 1.1 x 1.8: 1 -1,0; 2 1,0
0603 = smd 0.85 x 0.7: 1 -0.775,0; 2 0.775,0
L2825P = smd 1.4 x 2.4: 1 -1.2,0; 2 1.2,0
MCS08 = drill 1.194 pad 2.159 octagon: MP 0,0
DIL14S = drill 0.813 round: 1 -7.62,-3.81; 7 7.62,-3.81; 8 7.62,3.81; 14 -7.62,3.81
R0603 = smd 1 x 1.1: 1 -0.85,0; 2 0.85,0
R2512 = smd 1.8 x 3.2: 1 -2.8,0; 2 2.8,0
CAPOT_403.16 = smd 3 x 3: 1 0,0; 2 78,27; 3 0,27
CAPOT_MS355-10 = drill 0.8 pad 1.5 long: P$1 7.4,-9.35; P$2 35.2,-6.75; P$3 19.9,9.35
SOT223 = smd 1.219 x 2.235: 1 -2.311,-3.099; 2 0,-3.099; 3 2.311,-3.099 | smd 3.6 x 2.2: 4 0,3.099
TO92-EBC = drill 0.813 long: B 0,-1.27; C 2.54,-1.27; E -2.54,-1.27
EI42-1 = drill 1.118 pad 3.81 octagon: 1 -12.497,12.497; 5 -12.497,-12.497 | drill 1.118 pad 3.175 octagon: 6 12.497,-12.497; 7 12.497,-7.493; 9 12.497,7.493; 10 12.497,12.497
EI30-2 = drill 1.118 pad 3.81 octagon: 1 -10.008,10.008; 5 -10.008,-10.008; 6 10.008,-10.008; 7 10.008,-5.004; 9 10.008,5.004; 10 10.008,10.008

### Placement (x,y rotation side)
B1  11.6,24.1 180 bottom
B2  55.4,49.3 180 bottom
C1  88.8,59 180 bottom
C2  8.4,80.1 180 bottom
C3  72.3,64.5 90 bottom
C4  48.7,64.3 180 bottom
C5  45.6,61.3 90 bottom
C6  89.6,56.7 180 bottom
C7  22.4,13.6 270 top
C8  16,7 90 bottom
C9  42.5,8.1 270 top
C12  58,60 90 top
C13  50.1,54.5 270 bottom
C14  40.5,60.1 90 top
C15  78.4,63.5 180 bottom
C16  87.6,62 90 bottom
C17  73.6,53.7 270 bottom
C19  89.6,53.6 180 bottom
C20  51.7,70.9 90 bottom
C21  18.9,80.06 180 bottom
C22  17,75.9 180 bottom
C23  14.9,72.9 0 bottom
C24  28.9,56.2 270 bottom
C25  89.6,46.6 270 bottom
C26  32,54.6 270 bottom
C27  25.7,55.6 270 bottom
C28  86.5,46 270 bottom
C29  22.6,55.6 270 bottom
C30  77,50 0 bottom
C31  14.9,69.6 0 bottom
C32  14.8,63.4 270 top
C33  13,63.4 270 top
C34  11.2,63.4 270 top
C35  31.1,64.3 90 bottom
C36  26.1,77 0 bottom
C37  25.19,72.53 45 bottom
C38  20.5,72.3 90 bottom
C39  29.19,81.07 225 bottom
C40  27.6,64.6 90 bottom
C41  48.4,70.9 90 bottom
C42  55.5,59.5 180 bottom
C43  54.2,62.9 90 bottom
C44  64.9,55.9 270 bottom
C45  61.7,55.2 270 bottom
C46  64.2,62.9 90 bottom
C47  61.8,62.3 90 bottom
C48  89.8,68.2 90 bottom
C49  91.7,72.2 90 bottom
C50  91.9,64.3 180 bottom
C51  94.2,71.3 180 bottom
C52  92.4,74.8 180 bottom
C53  81.3,70.6 90 bottom
C54  84.5,70 90 bottom
C55  88.8,51.1 180 bottom
C56  70.7,70.8 90 bottom
C57  67.1,71.3 90 bottom
C58  54.8,70.5 90 bottom
F2  14.3,67.4 180 top
F3  84.5,63.4 90 bottom
F4  80.9,47.1 180 bottom
F5  60.5,69.5 180 bottom
IC1  22.9,79.8 180 bottom
IC2  31.6,3.1 180 top
IC3  68.4,57.2 90 bottom
IC4  68.4,62.4 90 bottom
IC5  30.9,59.3 180 bottom
IC6  12.1,77.8 180 bottom
IC7  49.7,60.8 270 bottom
J1  104.3,27.5 180 top
J2  111,90.1 90 top
J3  107.8,67.4 270 top
J4  7.5,11.5 90 top
J5  5.5,80.1 180 top
JP1  96.6,82.3 270 top
JP2  83.4,52.5 0 top
JP3  29.8,69.7 0 top
JP4  67,83.6 0 top
JP5  79.2,69.8 0 top
JP6  73.6,69.8 0 top
JP7  6,58.9 90 top
L1  105,85.2 135 bottom
L2  15.8,78.3 90 bottom
L3  26.6,80.3 90 bottom
L4  19.7,69.6 180 bottom
L5  92.4,68.2 270 bottom
L6  89.3,72.3 270 bottom
L7  88.3,76.2 180 bottom
LSP1  80.5,9.7 0 top
LSP2  76.1,9.7 0 top
LSP3  76.1,13.4 0 top
LSP4  80.4,13.4 0 top
QG1  94.9,55 90 top
R1  74.1,64.6 270 bottom
R2  31.6,12.5 270 bottom
R3  43.7,61.4 270 bottom
R4  51.6,6.5 90 bottom
R5  53.3,6.5 90 bottom
R6  36,7.7 90 bottom
R7  36.9,5.1 0 bottom
R8  79.1,60 180 bottom
R9  79.1,56 180 bottom
R10  34.1,54.7 90 bottom
R11  29.8,74.1 270 bottom
R12  31.1,76.2 0 bottom
R13  31.1,72 0 bottom
R15  3,6.7 90 bottom
R16  24.4,63 0 bottom
SH1  22.5,66.9 0 top
SH2  0.8,77 180 bottom
T1  6.6,11.5 270 bottom
T2  51.73,9.23 180 top
TR1  55.5,34.6 90 top
TR2  16.2,37.6 180 top

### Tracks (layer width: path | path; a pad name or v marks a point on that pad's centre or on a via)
+1V2
  Bottom 0.3: IC7.10 IC7.9
  Bottom 1: 54.9,69.5 F5.1 | C58.1 54.8,69.6 54.9,69.5 | 54.9,69.5 C20.1 C41.1 47.65,68.75 47.65,64.3 C4.1 47.5,63.95 IC7.10
+3V3
  pour Bottom (no thermals): 81.3,61.3 82.6,61.3 83.3,60.6 85.7,60.6 86.3,61.2 88.8,61.2 88.8,60.2 88.3,59.7 88.3,58.1 88.8,57.6 88.8,52.4 88.3,51.9 88.3,50.8 85.8,50.8 85.4,51.2 85.4,53.9 84.7,54.6 81.3,54.6
+5V  (via drill 0.6)
  Top 1: F2.3 C34.1 C33.1 C32.1 18.05,64.25 v22.6,59.7 | v22.6,59.7 v22.6,58.5 | JP2.1 75.3,52.5 74.2,51.4 30.9,51.4 v22.6,59.7
  Bottom 0.3: IC5.10 IC5.9
  Bottom 0.5: C24.1 28.9,57.25
  Bottom 1: 25.7,57.05 22.65,57.05 C29.1 v22.6,58.5 v22.6,59.7 | 25.7,57.05 C24.1 28.95,57.1 IC5.10 | 25.7,57.05 C27.1
D+
  Bottom 0.7: L1.P$1 106.6,86.02 106.6,86.1 107.8,87.3 107.8,88.5 108.15,88.85 J2.3
D+*
  Bottom 0.7: JP1.2 97.37,81.8 102.3,81.8 104,83.5 104.08,83.5 L1.P$2
D-
  Bottom 0.7: L1.P$4 105.92,86.9 106,86.9 106.8,87.7 106.8,88.4 106.35,88.85 J2.2
D-*
  Bottom 0.7: JP1.1 97.37,82.8 101.9,82.8 103.4,84.3 103.4,84.38 L1.P$3
DTR
  Bottom 0.8: R5.1 53.3,5.4 55,3.7 105.6,3.7 110.8,8.9 110.8,41.3 102.2,49.9 102.2,61.8 105,64.6 106.47,64.6 J3.4
GND  (via drill 0.3)
  Bottom 0.25: IC3.5 67.1,58.2 v67.7,58.8 | IC3.EXP IC3.8 73.3,57.2 73.7,57.6 | IC4.5 v66.2,64.9
  Bottom 0.3: IC7.8 IC7.EXP | IC7.5 51.9,58.7 v51.8,58.6 | IC5.EXP IC5.8 30.9,55.8 30.7,55.6 | IC5.5 31.9,60.7 32.1,60.5 32.5,60.5 | 74.5,61.9 73.1,61.9 72.6,62.4 IC4.8 IC4.EXP
  Bottom 0.5: 64.1,63.8 61.8,63.8 C47.2
  other vias: 9.7,81.3 12.5,65.7 14.5,65.7 16.5,65.7 18.5,65.7 9.7,62.5 9.7,64.5 9.7,66.5 11.2,61.2 13,61.2 14.8,61.2 16.2,62.6 11,81.3 12.3,81.3 13.6,81.3 14.9,81.3 16.2,81.3 17.5,81.3 11.5,80.2 12.7,80.2 12.7,79.2 11.5,79.2 11.5,78.2 12.7,78.2 12.7,77.2 12.7,76.2 11.5,77.2 11.5,76.2 10.4,77.1 10.4,78.1 14.4,78.2 13.7,76.6 14.7,76.2 14.8,75.2 14.8,74.2 13.6,77.6 13.4,74.1 12.9,70.3 13.2,71.8 14.9,71.2 12.9,72.9 12.8,69.1 16.7,70.7 18,70.7 19.3,70.7 16.9,72 17,73.3 16.7,74.6 17.9,74.7 19.3,72 19.4,73.3 19.1,76 18.8,77.1 17.3,77.7 18.3,78.3 19.5,78.9 18.8,81.4 19.7,82.3 20.7,83.2 22,83.3 23.3,83.3 24.6,83.3 25.9,83.3 27.2,83.3 28.5,83.3 22.3,82.3 23.5,82.3 22.3,81.3 23.5,81.3 23.5,80.3 22.3,80.3 22.3,79.3 22.3,78.3 23.5,79.3 23.5,78.3 20.8,79.1 21.5,79.8 21.3,78.2 24.3,79.7 25.2,80.2 25,79 24.5,78.1 25.7,78.2 24.1,77 24.5,75.9 25.8,75.8 25.8,73.7 24.9,74.5 23.8,74 24.1,72 22.9,72 21.7,72 21.6,73.2 20.6,74.3 22.5,75.3 20.8,76.3 22.4,76.8 20.1,77.5 18.6,68.5 18.6,67.1 9.6,67.9 11.3,69.1 21.6,69.1 21.6,70.3 23,70.3 24.3,70.3 25.6,70.3 26.5,70.8 27.2,71.5 27.8,72.3 27.9,73.3 27.9,74.3 27.9,75.3 28.2,77.2 28.1,78.2 28.1,79.2 28.1,80.2 28.2,76.2 29.6,82.5 30.5,81.5 31.3,80.4 31.4,79.1 31.4,77.5 32.8,77.3 32.9,75.2 31.4,75 33.1,76.3 31,74.1 31.4,73.2 32.7,73.2 33.1,72 32.5,70.8 28.2,70.6 28.2,69.3 28.9,68.2 30.2,68.1 31.2,68.9 31.6,70.1 8.1,67.9 6.7,67.9 5.2,67.9 3.8,67.9 2.4,67.9 1,67.9 0.8,69.2 0.8,70.6 0.8,72 0.8,73.4 0.8,74.8 0.8,76.2 0.8,77.6 0.8,79 0.8,80.4 0.8,81.8 0.8,83.2 0.8,84.6 0.8,86.3 2.2,86.3 3.6,86.3 5,86.3 6,86.3 10.4,86.3 11.8,86.3 13.2,86.3 14.6,86.3 16,86.3 17.4,86.3 18.8,86.3 20.2,86.3 21.6,86.3 23,86.3 24.4,86.3 25.8,86.3 27.2,86.3 28.6,86.3 30,86.3 31.4,86.3 32.8,86.3 34.2,86.3 35.9,86.3 36,81.4 36,80 36,78.6 36,77.2 36,75.8 36,74.4 36,73 36,71.6 36,70.2 36,68.8 36,67.6 34.6,67.5 33.2,67.5 31.8,67.5 27.4,67.5 26,67.5 24.6,67.5 23.2,67.5 79,48.8 80.4,48.8 81.6,48.8 82.8,48.8 84,49 85.4,49.1 87.4,49.1 89.4,49.1 91.4,48.9 92.9,47.6 91.7,46 90.3,44.6 88.4,46 88.5,43.7 86.5,43.2 84.5,43.6 84.5,45.4 82.5,45.4 80.5,45.4 78.5,45.4 76.6,46 76.6,48 75.5,48.9 75,50.3 76.3,51.1 78,51.2 79.6,51.2 91.1,61.2 89.7,62.3 92.7,62.3 93.9,64 89.7,64.3 89.7,65.9 88.6,67.5 88.6,69.6 88.6,68.6 88.8,66.3 92.4,65.6 94.1,65.7 94.4,67 94.4,68.4 94.4,69.8 95.7,70.2 96.2,71.3 95.6,72.5 94.3,72.5 92.9,72.5 92.9,73.6 94.4,74 94.4,75.5 92.7,76 90.9,76 87.4,70.3 87.4,71.7 87.4,73.1 87.4,74.3 86.1,74.4 85.4,75.6 85.2,77 85.2,78.4 90.9,77.4 89.8,78.1 88.4,78.1 88.4,79.5 87.8,80.7 86.8,81.7 85.8,82.7 84.5,79.6 83.5,80.6 82.5,81.6 84.9,83.7 83.9,84.6 82.6,85.1 81.2,85.1 79.8,85.1 81.2,82 79.8,82 78.4,82 77,82 75.6,82 78.4,85.1 77,85.1 75.6,85.1 74.2,85.1 72.8,85.1 71.4,85.1 70,85.1 68.6,85.1 67.2,85.3 65.8,84.9 65.2,83.6 65.7,82.3 67,81.8 68.4,82 69.8,82 71.2,82 72.6,82 74.1,82 84.6,73 82.5,70.4 81.2,72.7 79.8,71.7 78,71.2 77.5,69.4 78.7,68 80.2,68.5 81.5,67.8 86.6,68.7 86.4,67.2 86.1,65.2 82.7,67.1 82.8,65.6 82.8,64.1 87.6,64.8 82.8,62.6 82.7,72.8 96.4,66.8 98.4,66.8 100.4,66.8 100.4,68.8 100.4,70.8 100.4,72.8 100.4,74.8 100.4,76.8 100.4,78.8 99.8,80.9 98.6,80 96.8,79.4 94.8,79.8 94.5,81.8 94.3,83.8 95.8,85.1 97.8,85.1 99.4,83.8 100.8,83.8 104.5,86.9 100.5,88.5 100.5,86.9 104.8,88.9 104.8,90.9 105.6,92.7 107.6,92.8 109.6,92.8 109.8,91.3 109.6,88.9 109.2,87.8 108.5,86.7 103.8,86 102.9,85.2 102,84.3 103.8,82 102.8,81 105.6,66 104.1,65.3 102.6,63.9 101.2,62.4 101,60.4 101,58.4 101,56.3 101,54.3 101,52.3 101,50.2 102,48.5 103.4,47.1 104.8,45.7 106.3,44.2 107.7,42.8 109,41.4 109.6,39.6 109.6,37.6 109.6,35.6 109.6,33.6 109.6,31.6 109.6,29.6 109.6,27.6 109.6,25.6 109.6,23.6 109.6,21.6 109.6,19.6 109.6,17.6 109.6,15.6 109.6,13.6 109.6,11.6 109.7,9.6 108.4,8.1 107,6.7 105.5,5.4 103.6,4.8 101.6,4.8 99.6,4.8 97.6,4.8 95.6,4.8 93.6,4.8 91.5,4.8 89.5,4.8 87.5,4.8 85.5,4.8 83.5,4.8 81.5,4.8 79.5,4.8 77.5,4.8 75.5,4.8 73.5,4.8 71.5,4.8 69.5,4.8 67.5,4.8 65.5,4.8 63.5,4.8 61.5,4.8 59.5,4.8 57.8,4.8 54.7,5.6 54.6,7.6 38.2,14.7 36.2,14.7 34.2,14.7 32.2,14.7 30.2,14.7 28,14.7 26.3,15.9 24.9,17.4 23,18.1 21.2,19.1 19.8,20.6 18.3,22 16.3,22.3 14.3,22.3 12.2,22.5 11.6,21 12.4,19.7 14.4,19.8 16.4,19.8 18.1,18.7 19.4,17.3 20.4,15.5 0.6,12.5 0.6,14.5 0.6,16.5 0.6,18.5 0.6,20.5 0.6,22.5 0.7,0.7 0.6,2.5 0.6,4.5 0.6,6.5 0.6,8.5 0.6,10.5 12.5,0.6 10.5,0.6 8.5,0.6 6.5,0.6 4.5,0.6 2.5,0.6 24.5,0.6 22.5,0.6 20.5,0.6 18.5,0.6 16.5,0.6 14.5,0.6 36.5,0.6 34.5,0.6 32.5,0.6 30.5,0.6 28.5,0.6 26.5,0.6 48.5,0.6 46.5,0.6 44.5,0.6 42.5,0.6 40.5,0.6 38.5,0.6 0.6,24.5 0.6,26.5 0.6,28.5 0.6,30.5 0.6,32.5 0.6,34.5 0.6,36.5 0.6,38.5 0.6,40.5 0.6,42.5 0.6,44.5 0.6,46.5 0.6,48.4 0.6,50.4 0.6,52.4 0.6,54.4 0.6,56.4 0.6,58.4 0.6,60.4 0.6,62.4 0.6,64.4 0.6,66.4 50.5,0.6 62.5,0.6 60.5,0.6 58.5,0.6 56.5,0.6 54.5,0.6 52.5,0.6 74.5,0.6 72.5,0.6 70.5,0.6 68.5,0.6 66.5,0.6 64.5,0.6 86.5,0.6 84.5,0.6 82.5,0.6 80.5,0.6 78.5,0.6 76.5,0.6 98.5,0.6 96.5,0.6 94.5,0.6 92.5,0.6 90.5,0.6 88.5,0.6 110.5,0.6 108.5,0.6 106.5,0.6 104.5,0.6 102.5,0.6 100.5,0.6 118.9,2.5 118.8,0.7 117.4,0.6 116,0.6 114.5,0.6 112.5,0.6 118.9,14.5 118.9,12.5 118.9,10.5 118.9,8.5 118.9,6.5 118.9,4.5 101.5,65.4 10.2,22.9 8.2,22.9 6.2,22.9 4.2,22.9 2.2,22.9 2.5,52.4 4.5,52.4 6.5,52.4 8.5,52.4 10.5,52.4 12.5,52.4 14.1,51.2 15.4,49.7 16,47.8 16.4,45.9 16.4,43.9 16.4,41.9 16.4,39.9 16.4,37.9 16.4,35.9 16.4,33.9 16.4,31.9 16.4,29.9 16.4,27.9 16.4,25.9 16.4,24.1 16.7,51.2 18.6,51.8 20.6,51.8 22.6,51.8 24.6,51.8 26.6,51.8 28.6,51.8 29.9,50.7 31.6,50.2 33.6,50.2 35.6,50.2 37.6,50.2 39.6,50.2 41.6,50.2 43.6,50.2 45.6,50.2 47.6,50.2 49.6,50.2 51.6,50.2 53.6,50.2 55.6,50.2 57.6,50.2 59.6,50.2 61.6,50.2 63.6,50.2 65.6,50.2 67.6,50.2 69.6,50.2 71.6,50.2 73.3,50.2 93.3,45 95.3,45 97.3,45 99.3,45 101.3,45 103.1,45 0.6,88.3 0.6,90.3 0.6,92.3 0.6,94.3 0.6,96 0.6,97.4 0.7,98.8 12.5,98.9 10.5,98.9 8.5,98.9 6.5,98.9 4.5,98.9 2.5,98.9 24.5,98.9 22.5,98.9 20.5,98.9 18.5,98.9 16.5,98.9 14.5,98.9 36.5,98.9 34.5,98.9 32.5,98.9 30.5,98.9 28.5,98.9 26.5,98.9 48.5,98.9 46.5,98.9 44.5,98.9 42.5,98.9 40.5,98.9 38.5,98.9 50.5,98.9 62.5,98.9 60.5,98.9 58.5,98.9 56.5,98.9 54.5,98.9 52.5,98.9 74.5,98.9 72.5,98.9 70.5,98.9 68.5,98.9 66.5,98.9 64.5,98.9 86.5,98.9 84.5,98.9 82.5,98.9 80.5,98.9 78.5,98.9 76.5,98.9 98.5,98.9 96.5,98.9 94.5,98.9 92.5,98.9 90.5,98.9 88.5,98.9 110.5,98.9 108.5,98.9 106.5,98.9 104.5,98.9 102.5,98.9 100.5,98.9 118.8,98.8 117.4,98.9 116,98.9 114.5,98.9 112.5,98.9 118.9,28.5 118.9,30.5 118.9,32.5 118.9,34.5 118.9,36.5 118.9,38.5 118.9,18.5 118.9,20.5 118.9,22.5 118.9,24.5 118.9,26.5 118.9,40.5 118.9,42.5 118.9,44.5 118.9,46.5 118.9,48.5 118.9,50.5 118.9,52.5 118.9,54.5 118.9,56.5 118.9,58.5 118.9,60.5 118.9,62.5 118.9,64.4 118.9,66.4 118.9,68.4 118.9,70.4 118.9,72.4 118.9,74.4 118.9,76.4 118.9,78.4 118.9,80.4 118.9,82.4 118.9,16.5 118.9,84.4 118.9,86.4 118.9,88.4 118.9,90.4 118.9,92.4 118.9,94.4 118.9,95.9 118.9,97.3 32.6,61.3 32.6,59.7 32.6,58.2 30.3,59.8 30.3,58.8 31.5,58.8 31.5,59.8 29.2,60.2 29.2,58.3 34,58.2 35.3,58.2 36.5,58.2 35.2,59.5 34,60.6 27.6,53 20.6,53.2 20.6,55.2 20.6,57.2 21.4,58.5 20.4,60.2 19,61.6 17.8,62.8 19.6,64.5 20.7,63.3 22.3,61.8 24,60 25.4,58.6 27.3,58.5 27.2,60.2 25.6,60.2 24,61.7 25.8,61.8 28.8,61.7 25.4,66 29.8,65.1 29.7,66.8 31.1,66.4 32.5,65.1 36.3,62.5 37.7,61.1 39.1,59.7 30.3,55.9 30.3,54 32,52.6 34.1,52.6 35.4,53.9 35.4,56.1 37.4,56.2 39.4,56 37.6,66.8 39.4,66.8 41.2,66.8 43,66.8 44.8,66.8 46.5,66.8 46.5,64.8 45.2,63.5 43.3,63.3 48.9,58.6 50.4,58.6 48.8,62.8 52.1,63 50.6,62.8 50.7,64.5 52.3,64.5 49.5,65.4 48.8,66.8 50.6,66.8 52.4,66.8 54.2,66.8 56,66.8 56.4,64.3 41.1,54.8 43,54.2 45,54.2 47,54.2 48.9,53.6 51.2,52.6 54.5,52.6 55.6,54.3 57.2,55.6 59.2,55.6 46.3,68.8 46.3,70.8 46.3,72.8 48,73.9 50,73.9 52,73.9 53.7,72.9 55.7,72.5 56.1,70.8 58,71.3 58,66.8 60,66.8 62,66.8 64,66.8 66,66.8 60,71.3 62,71.3 64,71.3 65.1,72.7 66.3,74.2 68.3,74.2 69.1,72.8 69.4,71.1 70.9,72.8 71.9,71 68,66.8 70,66.8 72,66.8 74,66.8 76,66.8 77.6,66.8 73.9,71.5 75.4,70.2 75,68.2 59.6,54.1 56.5,52.6 59.6,52.6 63.7,52.6 63.7,55.1 66.3,55.3 65,53.8 67.4,55.6 68.4,55.6 69.4,55.6 69.2,58.8 66.2,58.9 67.3,60.7 69.5,60.7 68.4,60.7 64.3,65 67.9,64.9 69.6,64.6 68.4,63.9 70.8,59.9 62.7,65.2 61,65.2 59.6,64.2 59.8,59.5 81.3,63.5 79.8,65.6 81.3,65.1 79.1,61 79.1,59 79.1,57 79.1,55 71.5,52.6 69.4,52.6 67.4,52.6 65.7,52.6 74.3,62.2 75.4,63.3 75.4,65 72.5,58.9 73.2,57.7 71.2,53.9 70.3,54.9 75.4,53.7 77.1,53.7 78.5,53.8 57.9,65 89.7,60.3 91,59.1 92.5,58.2 92.5,56.3 92.5,54.4 92.5,52.5 91.1,51.2 90.5,49.9 22.5,88.2 22.5,90.2 22.5,92.2 22.5,93.9 24.5,93.9 26.5,93.9 28.5,93.9 30.5,93.9 32.5,93.9 34.5,93.9 36.5,93.9 38.5,93.9 40.5,93.9 42.5,93.9 44.5,93.9 46.5,93.9 48.5,93.9 50.5,93.9 52.5,93.9 54.5,93.9 56.5,93.9 58.5,93.9 60.5,93.9 62.5,93.9 64.5,93.9 66.5,93.9 68.5,93.9 70.5,93.9 72.5,93.9 74.5,93.9 76.5,93.9 78.5,93.9 80.5,93.9 82.5,93.9 84.5,93.9 86.5,93.9 88.5,93.9 90.5,93.9 92.5,93.9 94.5,93.9 96.5,93.9 98.5,93.9 100.5,93.9 100.5,91.9 100.5,90.2 37.6,48.2 37.6,46.2 37.6,44.2 37.6,42.2 39,40.8 41,40.7 43,40.7 45,40.7 47,40.7 49,40.7 51,40.7 53,40.7 55,40.7 57,40.7 59,40.7 61,40.7 63,40.7 65,40.7 67,40.7 69,40.7 71,40.7 73,40.7 74.4,42.1 75.8,43.5 77,44.5 49.2,61.4 50.2,61.4 50.2,60.2 49.2,60.2 67.9,63 68.9,63 68.9,61.8 67.9,61.8 67.9,57.8 68.9,57.8 68.9,56.6 67.9,56.6 107.7,85.8 106.7,84.8 105.7,83.8 104.8,82.9 101.4,80.9 100.5,85.3 105.4,87.8 56,4.8 40.1,14.7 41.9,14.7 43.7,14.7 45.6,14.7 47.4,14.7 48.8,13.7 49.9,12.6 51.4,12.6 53,12.5 52.9,8.7 33,12.7 35,12.7 36.9,12.7 38.7,12.7 40.6,12.7 42.4,12.7 44.2,12.7 46,12.7 47.7,12.2 30.3,12.3 28.8,13 25.3,13 26.7,11.9 11.4,12.7 16,9.2 27.4,5.9 26.5,4.4 34,64.6 35.2,63.6 27.4,61.8 22.2,64 23.9,64.3 25.4,64.5
  pour Bottom (rank 6): 119.5,0 119.5,99.5 0,99.5 0,0
  pour Top (rank 6): 0,0 119.5,0 119.5,99.5 0,99.5
N$1
  Bottom 1.5: J1.P 99,25.77 99,16.7 92,9.7 LSP1.MP
N$2
  Bottom 0.3: IC7.7 45.85,60.3 C5.1
  Bottom 0.5: R3.2 45.6,60.55 C5.1
N$3
  Bottom 1: QG1.8 91.09,64.26 C50.1 91.05,67.05 91.1,67.1 92.3,67.1 L5.2 91.1,67 91,67.1 90.05,67.1 C48.1
N$4
  Bottom 1: C48.2 89.8,70.6 L6.2 91.7,71.1 | 91.7,71.1 92.4,71.1 | 92.4,71.1 93.15,71.1 C51.1 | 91.7,71.1 C49.1 | 92.4,71.1 L5.1
N$5  (via drill 0.3)
  Top 0.25: v71.8,58.2 71.8,61.1 v73.5,62.8
  Bottom 0.25: v71.8,58.2 71.3,57.7 IC3.7 | v73.5,62.8 73.5,63.15 R1.2 | C3.1 71.91,63.21 | 71.91,63.21 71.55,62.9 | IC4.7 71.6,62.9 71.91,63.21
  Bottom 1: C3.1 73.9,63.55 R1.2
N$6
  Bottom 0.5: C2.1 7,80.1
  Bottom 1.7: 7,80.1 J5.1
N$7
  pour Bottom (no thermals): 70.2,61.9 72.4,61.9 73,61.3 75.3,61.3 76.3,62.3 76.3,64.6 77.6,64.6 77.6,62.3 76.8,61.5 76.8,58.6 73.9,58.6 71.4,61.1 70.2,61.1
N$8
  Bottom 0.8: T2.B 51.73,7.48 R4.2 R5.2
N$9
  Bottom 1: L7.2 89.5,73.7 L6.1 91.3,73.5 91.7,73.1 C49.2 91.55,73.2 C52.1
N$10
  Bottom 0.5: T1.1 31.3,13.81 | 31.3,13.81 47.39,13.81 49.2,12 T2.C | R2.1 31.6,13.51 31.3,13.81
N$11
  pour Bottom (no thermals): 8.8,80.5 10.7,80.5 10.7,79 9.5,79 8.8,79.7
N$12
  Bottom 1: TR2.10 9.86,27.59 B1.~1
N$13
  Bottom 1.5: TR2.9 TR2.7
N$14
  Bottom 1: TR2.6 11.19,47.61 12.9,45.9 B1.~2
N$15
  Bottom 0.6: R6.2 36,9.7
  Bottom 1: T1.3 9.7,8.5 12,6.2 15.95,6.2 C8.1 23.25,6.15 | R2.2 31.6,10.9
  pour Bottom (no thermals): 12.8,6.2 22.8,6.2 27.7,11.1 42.7,11.1 43.3,10.5 43.3,9.8 42.8,9.3 33.9,9.3 32.1,7.4 32.1,4.7 31.9,4.5 31.3,4.5 31.1,4.7 31.1,7.6 30.3,8.4 27.9,8.4 24.3,4.8 12.8,4.8 9.2,8.4 9.2,9.2 9.8,9.2
N$16
  Bottom 1.5: B2.AC1 49.7,44.8 48.2,46.3 48.2,46.9 TR1.9
N$17
  Bottom 1.5: B2.AC2 61.2,44.8 63.1,46.7 63.1,46.99 TR1.7
N$18
  Bottom 0.6: R6.1 35.35,6.85 IC2.1 34.68,5.1 R7.2
  Bottom 0.8: R6.1 36.05,6.8
N$19
  Top 1: C7.+ 24.06,16.14 29.1,11.1 29.1,5.68 IC2.3
  Bottom 1: B1.+ 17.49,21.05 C7.+
N$21
  Bottom 1: J4.1 T1.4 3,11 R15.2
N$22
  pour Bottom (no thermals): 70.2,56.7 73.6,56.7 74.3,57.4 76.9,57.4 76.9,54.6 71.8,54.6 70.2,56.2
N$23
  Bottom 1.5: LSP2.MP LSP3.MP
N$24
  Bottom 0.6: R16.2 21.8,63 16.4,57.6 6.03,57.6 JP7.1
N$26
  Bottom 1: F4.1 77.8,49.85 C30.1 82.9,50 83.4,50.5 JP2.2
N$27
  Bottom 0.25: 31.4,56.3 31.6,56.1 31.65,56.1 C26.1
  Bottom 0.3: 31.4,56.3 IC5.7
  Bottom 0.5: R10.2 33.85,55.55 33.6,55.8 32.25,55.8 C26.1
N$28
  pour Bottom (no thermals): 13.5,80.5 18.4,80.5 18.4,79.5 17.9,79 13.5,79
N$29  (via drill 0.6)
  Top 1: F2.1 v17.4,69.6
  Bottom 0.3: L4.1 v17.4,69.6 C31.1 15.8,69.65 15.8,72.8 | 15.8,76 L2.1 | C22.1 15.9,75.9 15.8,76 | 15.8,72.8 15.8,76 | C23.1 15.75,72.85 15.8,72.8
N$30
  Bottom 1: QG1.14 91.02,47.45 C25.1 86.55,47.45 C28.1 84.3,47.4 F4.3
N$31
  pour Bottom (no thermals): 24.3,82.5 28.5,82.5 29.2,81.8 28.4,81 24.3,81
N$32
  Bottom 0.3: 24.9,71.1 arc90 26.65,72.95 26.65,77.1 | L4.2 arc90 20.5,69.62 C38.1 20.85,71.1 24.9,71.1 | 26.65,77.1 26.65,79.25 L3.1 | C36.1 26.75,77 26.65,77.1 | 25.79,71.91 C37.1 | 25.79,71.91 26,71.7 | 25.79,71.91 arc-90 24.98,71.1 24.9,71.1
N$33
  pour Bottom (no thermals): 21.5,80.9 21.5,82.4 21,82.4 19.4,80.8 19.4,79.7 20.3,79.7
N$34
  Bottom 0.5: 29.8,72.9 R11.2 | R13.2 29.9,72 29.8,72.1
  Bottom 1.7: JP3.1 29.8,72.1 29.8,72.9
N$35
  Bottom 1.1: 86.8,76.2 L7.1
  Bottom 1.7: 86.8,76.2 86.8,79.5 82.8,83.5 67.1,83.5 JP4.1
N$36
  Bottom 0.5: C39.2 29.79,80.01 29.8,80 | R11.1 29.8,75.5 | 29.8,76.2 R12.2
  Bottom 1.7: 29.8,75.5 29.8,76.2 29.8,80
N$37
  Bottom 1: JP5.1 79.25,69.75 C53.1 81.65,69.4 81.7,69.4 82.5,68.6 C54.1 F3.3
N$39
  Bottom 1: 67,69.8 63.9,69.8 F5.3 | 67,69.8 70.8,69.8 | 70.8,69.8 JP6.1 | 67,69.8 C57.1 | C56.1 70.7,69.9 70.8,69.8
NEUTRE
  Bottom 0.5: J1.N 91.17,20.93 90.6,21.1
  Bottom 1.5: 90.6,21.1 85.8,25.9 46.8,25.9 TR1.1 26.21,38.9 TR2.5
PHASE
  Bottom 1.5: TR2.1 32.21,27.59 41.4,18.4 64.29,18.4 TR1.5 76,22.1 80.4,17.7 LSP4.MP
V+
  Bottom 0.25: 30.3,61.9 30.4,61.8 | C35.1 30.5,63.2 30.3,63.1 | 31.95,57.25 32,57.2 32.1,57.2 | IC3.6 70.6,58.5 69.4,59.7 67.1,59.7 65.9,60.9 | IC4.6 70.6,65 69.8,65.8 65.7,65.8 65.2,65.3 65.2,62.1
  Bottom 0.3: 32,57.2 IC5.6 | IC5.2 IC5.3 | 30.4,61.8 IC5.2 | IC5.2 IC5.1
  Bottom 0.5: 32.1,57.2 39.1,57.2 39.4,57.5
  Bottom 1: C40.1 27.3,63.2 27.1,63 R16.1
  Bottom 1.5: 30.3,63.1 30.3,61.9 | 30.3,63.1 33.6,63.1 39.2,57.5 39.4,57.5 40.48,57.5 C14.+ | C40.1 30.3,63.2 30.3,63.1
  pour Bottom (no thermals): 52.1,53 53.2,53 56.6,56.4 65.5,56.4 65.7,56.2 66.6,56.2 66.6,57.2 65.6,57.2 65.1,57.7 65.1,59.8 66.6,61.3 66.6,62.3 64.5,62.3 63.7,61.5 61.1,61.5 60.7,61.1 60.7,59.1 60.2,58.6 55.2,58.6 55,58.8 55,62 54.9,62.1 51.7,62.1 51.5,61.9 51.5,60.8 52.4,60.8 52.6,60.6 52.6,57.9 52.1,57.4 48.4,57.4 47.9,57.9 47.9,59.6 47.7,59.8 47.2,59.8 47.1,59.7 47.1,58.5 46.8,58.2 40.2,58.2 39.9,57.9 39.9,57.1 42,55 51.2,55 52.1,54.1

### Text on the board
Top: SDR_CANFI v1 | F4CTZ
